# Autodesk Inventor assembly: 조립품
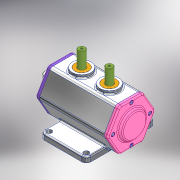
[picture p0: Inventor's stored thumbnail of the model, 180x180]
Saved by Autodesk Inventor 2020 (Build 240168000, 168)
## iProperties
Created: 2021-06
Part Number: 조립품
Document SubType Name: Assembly
Designer: 605-3
Author: 605-3
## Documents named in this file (11)
- C:\Users\605-3\Desktop\710606V1015\조립품.iam
- C:\Users\605-3\Desktop\710606V1015\본체.ipt
- C:\Users\605-3\Desktop\710606V1015\편심축.ipt
- C:\Users\605-3\Desktop\710606V1015\베어링 6203.ipt
- C:\Users\605-3\Desktop\710606V1015\앞커버.ipt
- C:\Users\605-3\Desktop\710606V1015\오일실.ipt
- C:\Users\605-3\Desktop\710606V1015\뒷커버.ipt
- C:\Users\605-3\Desktop\710606V1015\베어링 6302.ipt
- C:\Users\605-3\Desktop\710606V1015\부시.ipt
- C:\Users\605-3\Desktop\710606V1015\슬라이더.ipt
- C:\Users\605-3\Desktop\710606V1015\볼트 M4.ipt
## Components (10 placed, 3 different names)
1. 7-베어링 6203:1
2. 8-오일실:1
3. 9-M4-소켓머리:1
4. 9-M4-소켓머리:3
5. 9-M4-소켓머리:4
6. 9-M4-소켓머리:5
7. 9-M4-소켓머리:2
8. 9-M4-소켓머리:6
9. 9-M4-소켓머리:7
10. 9-M4-소켓머리:8
